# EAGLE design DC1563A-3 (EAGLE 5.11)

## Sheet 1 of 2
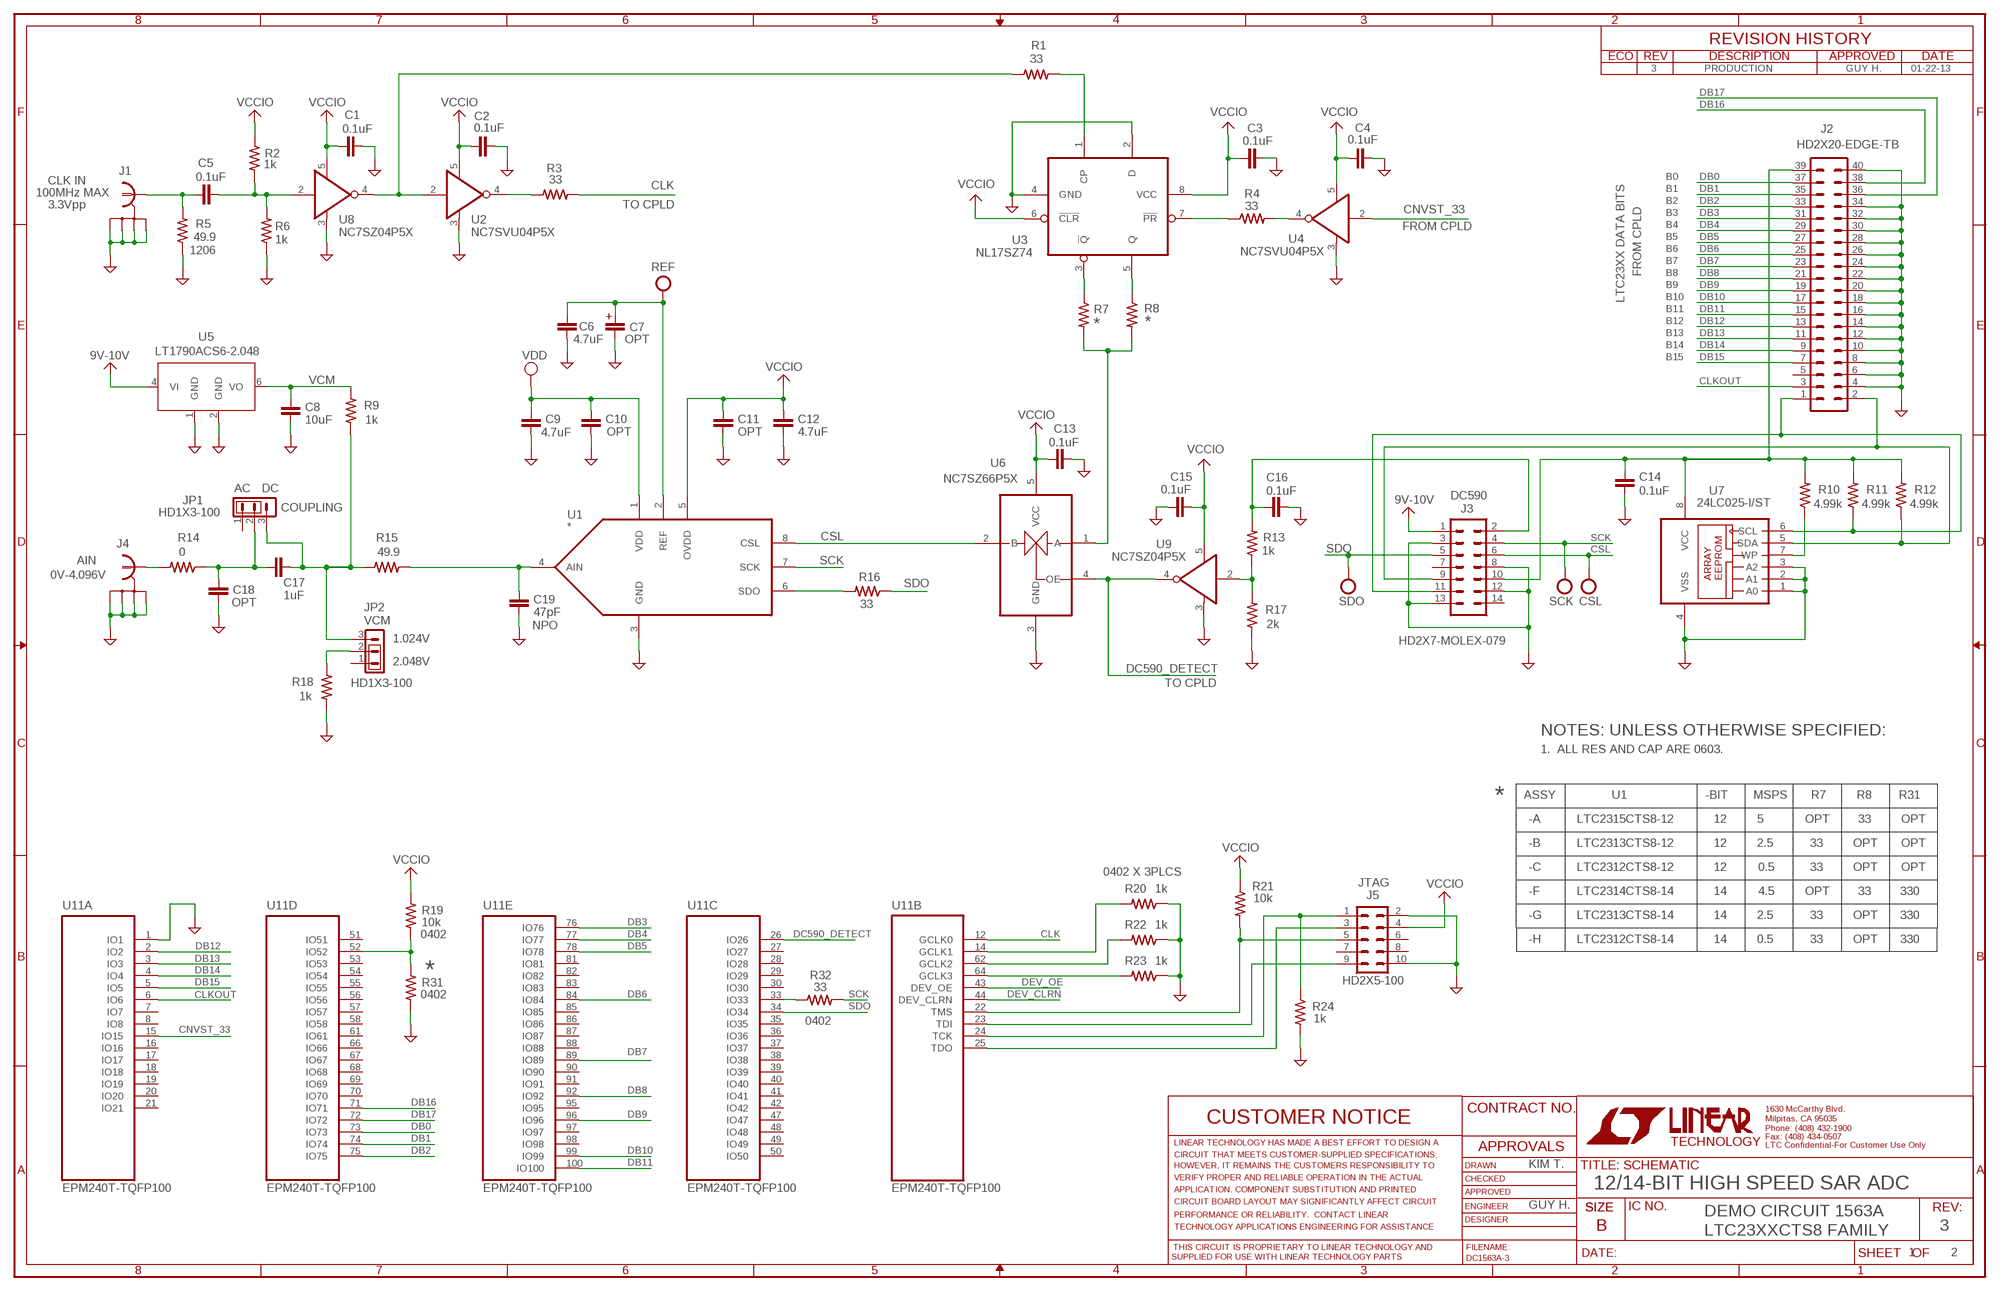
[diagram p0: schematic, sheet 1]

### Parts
C1  0.1uF  CAP-NP-SMT-0603  [0603]
C2  0.1uF  CAP-NP-SMT-0603  [0603]
C3  0.1uF  CAP-NP-SMT-0603  [0603]
C4  0.1uF  CAP-NP-SMT-0603  [0603]
C5  0.1uF  CAP-NP-SMT-0603  [0603]
C6  4.7uF  CAP-NP-SMT-0603  [0603]
C7  OPT  CAP-P-0603  [0603]
C8  10uF  CAP-NP-SMT-0603  [0603]
C9  4.7uF  CAP-NP-SMT-0603  [0603]
C10  OPT  CAP-NP-SMT-0603  [0603]
C11  OPT  CAP-NP-SMT-0603  [0603]
C12  4.7uF  CAP-NP-SMT-0603  [0603]
C13  0.1uF  CAP-NP-SMT-0603  [0603]
C14  0.1uF  CAP-NP-SMT-0603  [0603]
C15  0.1uF  CAP-NP-SMT-0603  [0603]
C16  0.1uF  CAP-NP-SMT-0603  [0603]
C17  1uF  CAP-NP-SMT-0603  [0603]
C18  OPT  CAP-NP-SMT-0603  [0603]
C19  47pF  CAP-NP-SMT-0603  [0603]
CSL  E-35-60  [PAD-35-60]
J1  BNC-5PINS  [BNC-112404]
J2  HD2X20-EDGE-TB  [CON-EDGE40-100]
J3  HD2X7-MOLEX-079  [HD2X7-079-MOLEX]
J4  BNC-5PINS  [BNC-112404]
J5  HD2X5-100  [HD2X5-100]
JP1  HD1X3-100  [HD1X3-100]
JP2  HD1X3-100  [HD1X3-100]
R1  33  RES-0603  [0603]
R2  1k  RES-0603  [0603]
R3  33  RES-0603  [0603]
R4  33  RES-0603  [0603]
R5  49.9  RES-1206  [1206]
R6  1k  RES-0603  [0603]
R7  *  RES-0603  [0603]
R8  *  RES-0603  [0603]
R9  1k  RES-0603  [0603]
R10  4.99k  RES-0603  [0603]
R11  4.99k  RES-0603  [0603]
R12  4.99k  RES-0603  [0603]
R13  1k  RES-0603  [0603]
R14  0  RES-0603  [0603]
R15  49.9  RES-0603  [0603]
R16  33  RES-0603  [0603]
R17  2k  RES-0603  [0603]
R18  1k  RES-0603  [0603]
R19  10k  RES-0402  [0402]
R20  1k  RES-0402  [0402]
R21  10k  RES-0603  [0603]
R22  1k  RES-0402  [0402]
R23  1k  RES-0402  [0402]
R24  1k  RES-0603  [0603]
R31  OPT  RES-0402  [0402]
R32  33  RES-0402  [0402]
REF  E-35-60  [PAD-35-60]
SCK  E-35-60  [PAD-35-60]
SDO  E-35-60  [PAD-35-60]
U1  *  LTC23XXCTS8  [TSOT23-8]
U2  NC7SVU04P5X  [SC70-5]
U3  NL17SZ74  [US8]
U4  NC7SVU04P5X  NC7ST04P5X  [SC70-5]
U5  LT1790ACS6-2.048  [SOT23-6]
U6  NC7SZ66P5X  [SC70-5]
U7  24LC025-I/ST  [TSSOP8]
U8  NC7SZ04P5X  [SC70-5]
U9  NC7SZ04P5X  [SC70-5]
U11  EPM240T-TQFP100  [TQFP100]

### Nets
9V-10V: J3.1 U5.4(VI) ; also sheet 2
CLK: R3.2 U11.12(B:GCLK0)
CLKOUT: J2.3 U11.6(A:IO6)
CNVST_33: U4.2(A) U11.15(A:IO15)
CSL: CSL.1 J3.6 U1.8(CSL) U6.2(B)
DB0: J2.37 U11.73(D:IO73)
DB1: J2.35 U11.74(D:IO74)
DB2: J2.33 U11.75(D:IO75)
DB3: J2.31 U11.76(E:IO76)
DB4: J2.29 U11.77(E:IO77)
DB5: J2.27 U11.78(E:IO78)
DB6: J2.25 U11.84(E:IO84)
DB7: J2.23 U11.89(E:IO89)
DB8: J2.21 U11.92(E:IO92)
DB9: J2.19 U11.96(E:IO96)
DB10: J2.17 U11.99(E:IO99)
DB11: J2.15 U11.100(E:IO100)
DB12: J2.13 U11.2(A:IO2)
DB13: J2.11 U11.3(A:IO3)
DB14: J2.9 U11.4(A:IO4)
DB15: J2.7 U11.5(A:IO5)
DB16: J2.38 U11.71(D:IO71)
DB17: J2.36 U11.72(D:IO72)
DC590_DETECT: U6.4(OE) U9.4(Y) U11.26(C:IO26)
DC590VP: C16.1 J3.2 R13.2
DEV_CLRN: U11.44(B:DEV_CLRN)
DEV_OE: U11.43(B:DEV_OE)
GND: C1.2 C2.2 C3.2 C4.2 C6.1 C7.2 C8.1 C9.1 C10.1 C11.1 C12.1 C13.2 C14.2 C15.1 C16.2 C18.2 C19.2 J1.2(GND) J1.3(GND) J1.4(GND) J1.5(GND) J2.4 J2.6 J2.8 J2.10 J2.12 J2.14 J2.16 J2.18 J2.20 J2.22 J2.24 J2.26 J2.28 J2.30 J2.32 J2.34 J2.40 J3.3 J3.8 J3.12 J3.13 J4.2(GND) J4.3(GND) J4.4(GND) J4.5(GND) J5.2 J5.10 R5.1 R6.1 R17.1 R18.1 R20.1 R22.1 R23.1 R24.2 R31.1 U1.3(GND) U2.3(GND) U3.2(D) U3.4(GND) U4.3(GND) U5.1(GND) U5.2(GND) U6.3(GND) U7.1(A0) U7.2(A1) U7.3(A2) U7.4(VSS) U8.3(GND) U9.3(GND) U11.1(A:IO1) ; also sheet 2
N$1: C17.1 C18.1 JP1.2 R14.1
N$2: J4.1 R14.2
N$3: J5.9 U11.23(B:TDI)
N$4: J5.1 R24.1 U11.24(B:TCK)
N$5: J5.3 U11.25(B:TDO)
N$6: J5.5 R21.2 U11.22(B:TMS)
N$9: R23.2 U11.64(B:GCLK3)
N$10: R7.1 U3.3(!Q)
N$11: R19.1 R31.2 U11.52(D:IO52)
N$12: R8.1 U3.5(Q)
N$13: R13.1 R17.2 U9.2(A)
N$15: R32.1 U11.33(C:IO33)
N$17: R10.1 U7.7(WP)
N$19: J2.1 J3.11 R11.1 U7.6(SCL)
N$23: R4.1 U3.7(!PR)
N$24: JP2.2 R18.2
N$25: R4.2 U4.4(Y)
N$26: C17.2 JP1.3 JP2.3 R9.1 R15.2
N$27: C5.1 J1.1 R5.2
N$28: C5.2 R2.1 R6.2 U8.2(A)
N$29: R1.2 U3.1(CP)
N$30: R22.2 U11.62(B:GCLK2)
N$31: R3.1 U2.4(Y)
N$32: R16.2 U1.6(SDO)
N$34: J2.2 J3.9 R12.1 U7.5(SDA)
N$36: R1.1 U2.2(A) U8.4(Y)
N$39: C6.2 C7.1 REF.1 U1.2(REF)
N$41: R7.2 R8.2 U6.1(A)
N$44: C19.1 R15.1 U1.4(AIN)
N$45: C14.1 J2.39 J3.10 R10.2 R11.2 R12.2 U7.8(VCC)
N$51: R20.2 U11.14(B:GCLK1)
SCK: J3.4 R32.2 SCK.1 U1.7(SCK)
SDO: J3.5 R16.1 SDO.1 U11.34(C:IO34)
VCCIO: C1.1 C2.1 C3.1 C4.1 C11.2 C12.2 C13.1 C15.2 J5.4 R2.2 R19.2 R21.1 U1.5(OVDD) U2.5(VCC) U3.6(!CLR) U3.8(VCC) U4.5(VCC) U6.5(VCC) U8.5(VCC) U9.5(VCC) ; also sheet 2
VCM: C8.2 R9.2 U5.6(VO)
VDD: C9.2 C10.2 U1.1(VDD) ; also sheet 2
Unconnected: J2.5 J3.7 J3.14 J5.6 J5.7 J5.8 JP1.1 JP2.1 U2.1(NC) U4.1(NC) U8.1(NC) U9.1(NC) U11.7(A:IO7) U11.8(A:IO8) U11.16(A:IO16) U11.17(A:IO17) U11.18(A:IO18) U11.19(A:IO19) U11.20(A:IO20) U11.21(A:IO21) U11.27(C:IO27) U11.28(C:IO28) U11.29(C:IO29) U11.30(C:IO30) U11.35(C:IO35) U11.36(C:IO36) U11.37(C:IO37) U11.38(C:IO38) U11.39(C:IO39) U11.40(C:IO40) U11.41(C:IO41) U11.42(C:IO42) U11.47(C:IO47) U11.48(C:IO48) U11.49(C:IO49) U11.50(C:IO50) U11.51(D:IO51) U11.53(D:IO53) U11.54(D:IO54) U11.55(D:IO55) U11.56(D:IO56) U11.57(D:IO57) U11.58(D:IO58) U11.61(D:IO61) U11.66(D:IO66) U11.67(D:IO67) U11.68(D:IO68) U11.69(D:IO69) U11.70(D:IO70) U11.81(E:IO81) U11.82(E:IO82) U11.83(E:IO83) U11.85(E:IO85) U11.86(E:IO86) U11.87(E:IO87) U11.88(E:IO88) U11.90(E:IO90) U11.91(E:IO91) U11.95(E:IO95) U11.97(E:IO97) U11.98(E:IO98)

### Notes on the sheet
- 3 | PRODUCTION | GUY H. | 01-22-13
- B0
- CLK IN
- B1
- 100MHz MAX
- B2
- 3.3Vpp | TO CPLD
- B3
- FROM CPLD | B4
- B5
- 1206 | B6
- B7
- FROM CPLD | B8
- B9
- LTC23XX DATA BITS | B10
- B11
- B12
- B13
- B14
- B15
- AC | DC
- DC590
- COUPLING
- AIN
- 0V-4.096V
- VCM
- NPO
- 1.024V
- 2.048V
- TO CPLD
- NOTES: UNLESS OTHERWISE SPECIFIED:
- 1.  ALL RES AND CAP ARE 0603.
- ASSY | U1 | -BIT | MSPS | R7 | R8 | R31
- *
- -A | LTC2315CTS8-12 | 12 | 5 | OPT | 33 | OPT
- -B | LTC2313CTS8-12 | 12 | 2.5 | 33 | OPT | OPT
- -C | LTC2312CTS8-12 | 12 | 0.5 | 33 | OPT | OPT
- 0402 X 3PLCS
- JTAG
- -F | LTC2314CTS8-14 | 14 | 4.5 | OPT | 33 | 330
- -G | LTC2313CTS8-14 | 14 | 2.5 | 33 | OPT | 330
- 0402
- -H | LTC2312CTS8-14 | 14 | 0.5 | 33 | OPT | 330
- *
- 0402
- 0402
- KIM T.
- 12/14-BIT HIGH SPEED SAR ADC
- GUY H.
- DEMO CIRCUIT 1563A
- 3
- LTC23XXCTS8 FAMILY
- 1 | 2

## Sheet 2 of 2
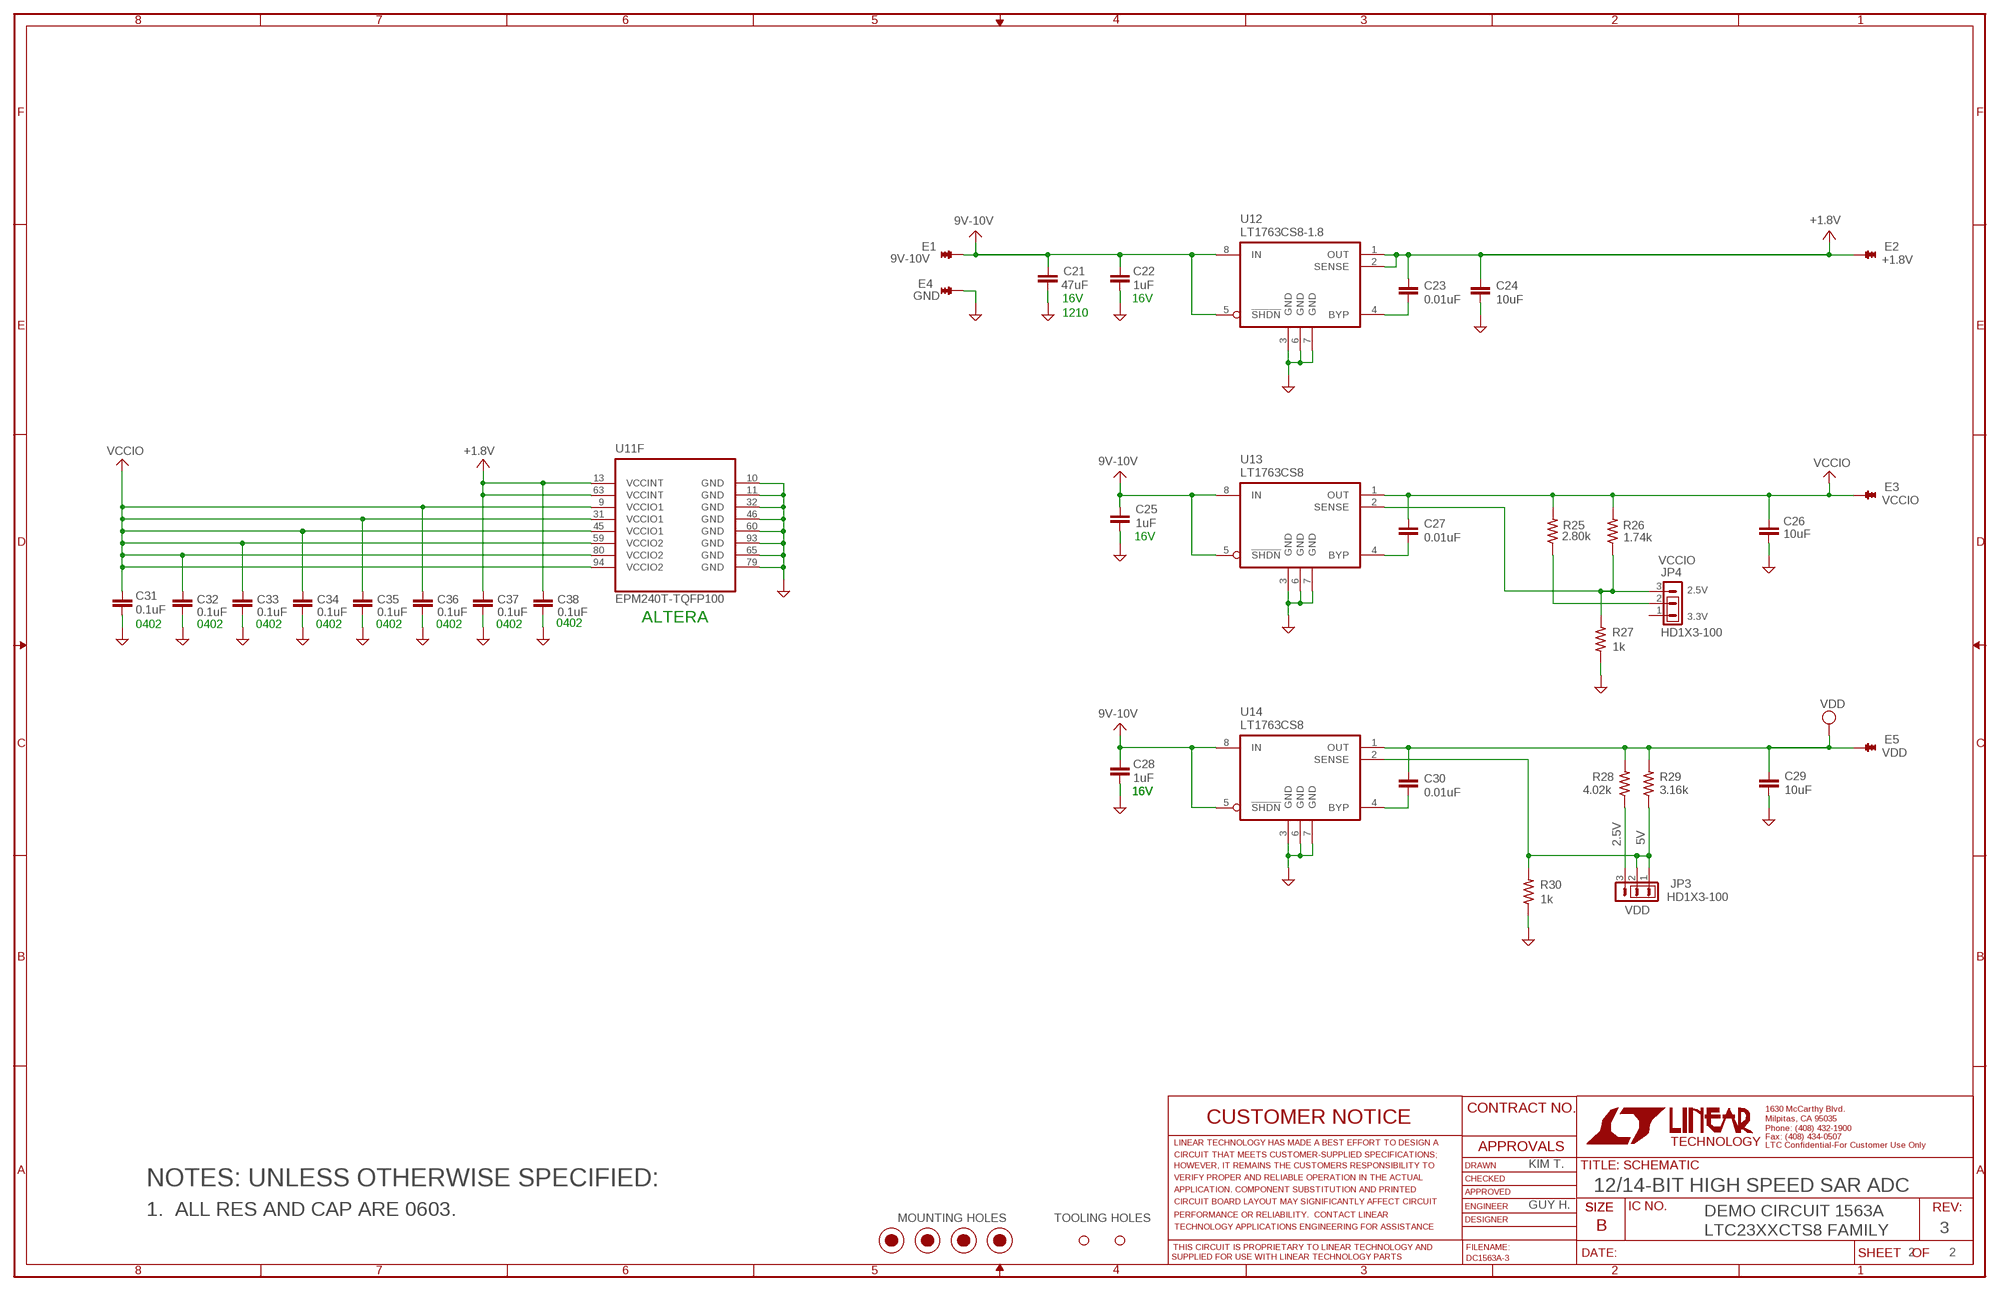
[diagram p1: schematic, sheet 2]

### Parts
C21  47uF  CAP-NP-SMT-1210  [1210]
C22  1uF  CAP-NP-SMT-0603  [0603]
C23  0.01uF  CAP-NP-SMT-0603  [0603]
C24  10uF  CAP-NP-SMT-0603  [0603]
C25  1uF  CAP-NP-SMT-0603  [0603]
C26  10uF  CAP-NP-SMT-0603  [0603]
C27  0.01uF  CAP-NP-SMT-0603  [0603]
C28  1uF  CAP-NP-SMT-0603  [0603]
C29  10uF  CAP-NP-SMT-0603  [0603]
C30  0.01uF  CAP-NP-SMT-0603  [0603]
C31  0.1uF  CAP-NP-SMT-0402  [0402]
C32  0.1uF  CAP-NP-SMT-0402  [0402]
C33  0.1uF  CAP-NP-SMT-0402  [0402]
C34  0.1uF  CAP-NP-SMT-0402  [0402]
C35  0.1uF  CAP-NP-SMT-0402  [0402]
C36  0.1uF  CAP-NP-SMT-0402  [0402]
C37  0.1uF  CAP-NP-SMT-0402  [0402]
C38  0.1uF  CAP-NP-SMT-0402  [0402]
E1  TURRET-094  [MILLMAX-2501-2]
E2  TURRET0.063  TURRET-064  [MILLMAX-2308-2]
E3  TURRET0.063  TURRET-064  [MILLMAX-2308-2]
E4  TURRET-094  [MILLMAX-2501-2]
E5  TURRET0.063  TURRET-064  [MILLMAX-2308-2]
JP3  HD1X3-100  [HD1X3-100]
JP4  HD1X3-100  [HD1X3-100]
MTG1  MTG-8831-8831  MTG-8831-STANDOFF  [MTG-8831]
MTG2  MTG-8831-8831  MTG-8831-STANDOFF  [MTG-8831]
MTG3  MTG-8831-8831  MTG-8831-STANDOFF  [MTG-8831]
MTG4  MTG-8831-8831  MTG-8831-STANDOFF  [MTG-8831]
R25  2.80k  RES-0603  [0603]
R26  1.74k  RES-0603  [0603]
R27  1k  RES-0603  [0603]
R28  4.02k  RES-0603  [0603]
R29  3.16k  RES-0603  [0603]
R30  1k  RES-0603  [0603]
U12  LT1763CS8-1.8  LT1763-1.8CS8  [SO8]
U13  LT1763CS8  [SO8]
U14  LT1763CS8  [SO8]
X1  TOOLINGHOLE-70MIL  [TOOLINGHOLE]
X2  TOOLINGHOLE-70MIL  [TOOLINGHOLE]

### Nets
9V-10V: C21.1 C22.1 C25.1 C28.1 E1.1 U12.5(!SHDN) U12.8(IN) U13.5(!SHDN) U13.8(IN) U14.5(!SHDN) U14.8(IN) ; also sheet 1
+1.8V: C23.1 C24.1 C37.1 C38.1 E2.1 U11.13(F:VCCINT) U11.63(F:VCCINT) U12.1(OUT) U12.2(SENSE)
GND: C21.2 C22.2 C24.2 C25.2 C26.2 C28.2 C29.2 C31.2 C32.2 C33.2 C34.2 C35.2 C36.2 C37.2 C38.2 E4.1 R27.1 R30.1 U11.10(F:GND) U11.11(F:GND) U11.32(F:GND) U11.46(F:GND) U11.60(F:GND) U11.65(F:GND) U11.79(F:GND) U11.93(F:GND) U12.3(GND) U12.6(GND) U12.7(GND) U13.3(GND) U13.6(GND) U13.7(GND) U14.3(GND) U14.6(GND) U14.7(GND) ; also sheet 1
N$7: JP4.3 R26.1 R27.2 U13.2(SENSE)
N$14: JP4.2 R25.1
N$18: JP3.1 JP3.2 R29.1 R30.2 U14.2(SENSE)
N$20: JP3.3 R28.1
N$50: C27.2 U13.4(BYP)
N$53: C23.2 U12.4(BYP)
N$57: C30.2 U14.4(BYP)
VCCIO: C26.1 C27.1 C31.1 C32.1 C33.1 C34.1 C35.1 C36.1 E3.1 R25.2 R26.2 U11.9(F:VCCIO1) U11.31(F:VCCIO1) U11.45(F:VCCIO1) U11.59(F:VCCIO2) U11.80(F:VCCIO2) U11.94(F:VCCIO2) U13.1(OUT) ; also sheet 1
VDD: C29.1 C30.1 E5.1 R28.2 R29.2 U14.1(OUT) ; also sheet 1
Unconnected: JP4.1 MTG1.1 MTG2.1 MTG3.1 MTG4.1 X1.1 X2.1

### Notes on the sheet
- 9V-10V | +1.8V
- GND | 16V | 16V
- 1210
- VCCIO
- 16V
- VCCIO
- 2.5V
- ALTERA | 3.3V
- 0402 | 0402 | 0402 | 0402 | 0402 | 0402 | 0402 | 0402
- VDD
- 16V | 16V
- 2.5V | 5V
- VDD
- KIM T.
- NOTES: UNLESS OTHERWISE SPECIFIED:
- 12/14-BIT HIGH SPEED SAR ADC
- GUY H.
- 1.  ALL RES AND CAP ARE 0603. | DEMO CIRCUIT 1563A
- MOUNTING HOLES | TOOLING HOLES
- LTC23XXCTS8 FAMILY | 3
- 2 | 2

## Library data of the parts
C1-C6 C8-C19 C21-C38 = LTDB_Passives:CAP-NP-SMT-: Capacitor; Non-polar; SMT
C7 = EagleLib:CAP-P: Capacitor; Non-polar; SMT
CSL SCK SDO = LTDB_Connectors:E-35-60
E1-E5 = LTDB_Connectors:TURRET: Turret
J1 J4 = LTDB_Connectors:BNC-5PINS: BNC CONNECTOR M/A COM www.macom.com distributor Farnell 149-452
J2 = EagleLib:HD2X20
J3 = LTDB_Connectors:HD2X7-MOLEX: HDR-7x2-Pin-Straight-Shrouded Molex 87331-1420
J5 = EagleLib:HD2X5
JP1-JP3 = LTDB_Connectors:HD1X3: Jumper,3pin, point connections
JP4 = EagleLib:HD1X3: Jumper,3pin, point connections
MTG1-MTG4 = LTDB_Connectors:MTG-8831
R1-R32 = LTDB_Passives:RES-: Resistor; GP
REF = DC1563A:E-35-60
U1 = EagleLib:LTC23XXCTS8
U2 = LTDB_ICs:NC7SVU04
U3 = LTDB_ICs:NL17SZ74
U4 = LTDB_ICs:NC7ST04
U5 = LTDB_Linear_Parts:LT1790?-*: Voltage Reference;Series
U6 = LTDB_ICs:NC7SZ66
U7 = LTDB_ICs:24LC025
U8 U9 = LTDB_ICs:NC7SZ04
U11 = LTDB_ICs:EPM240T-TQFP100
U12-U14 = LTDB_Linear_Parts:LT1763: 500MA, Low Noise, LDO Micropwer Regulator
X1 X2 = LTDB_Connectors:TOOLINGHOLE

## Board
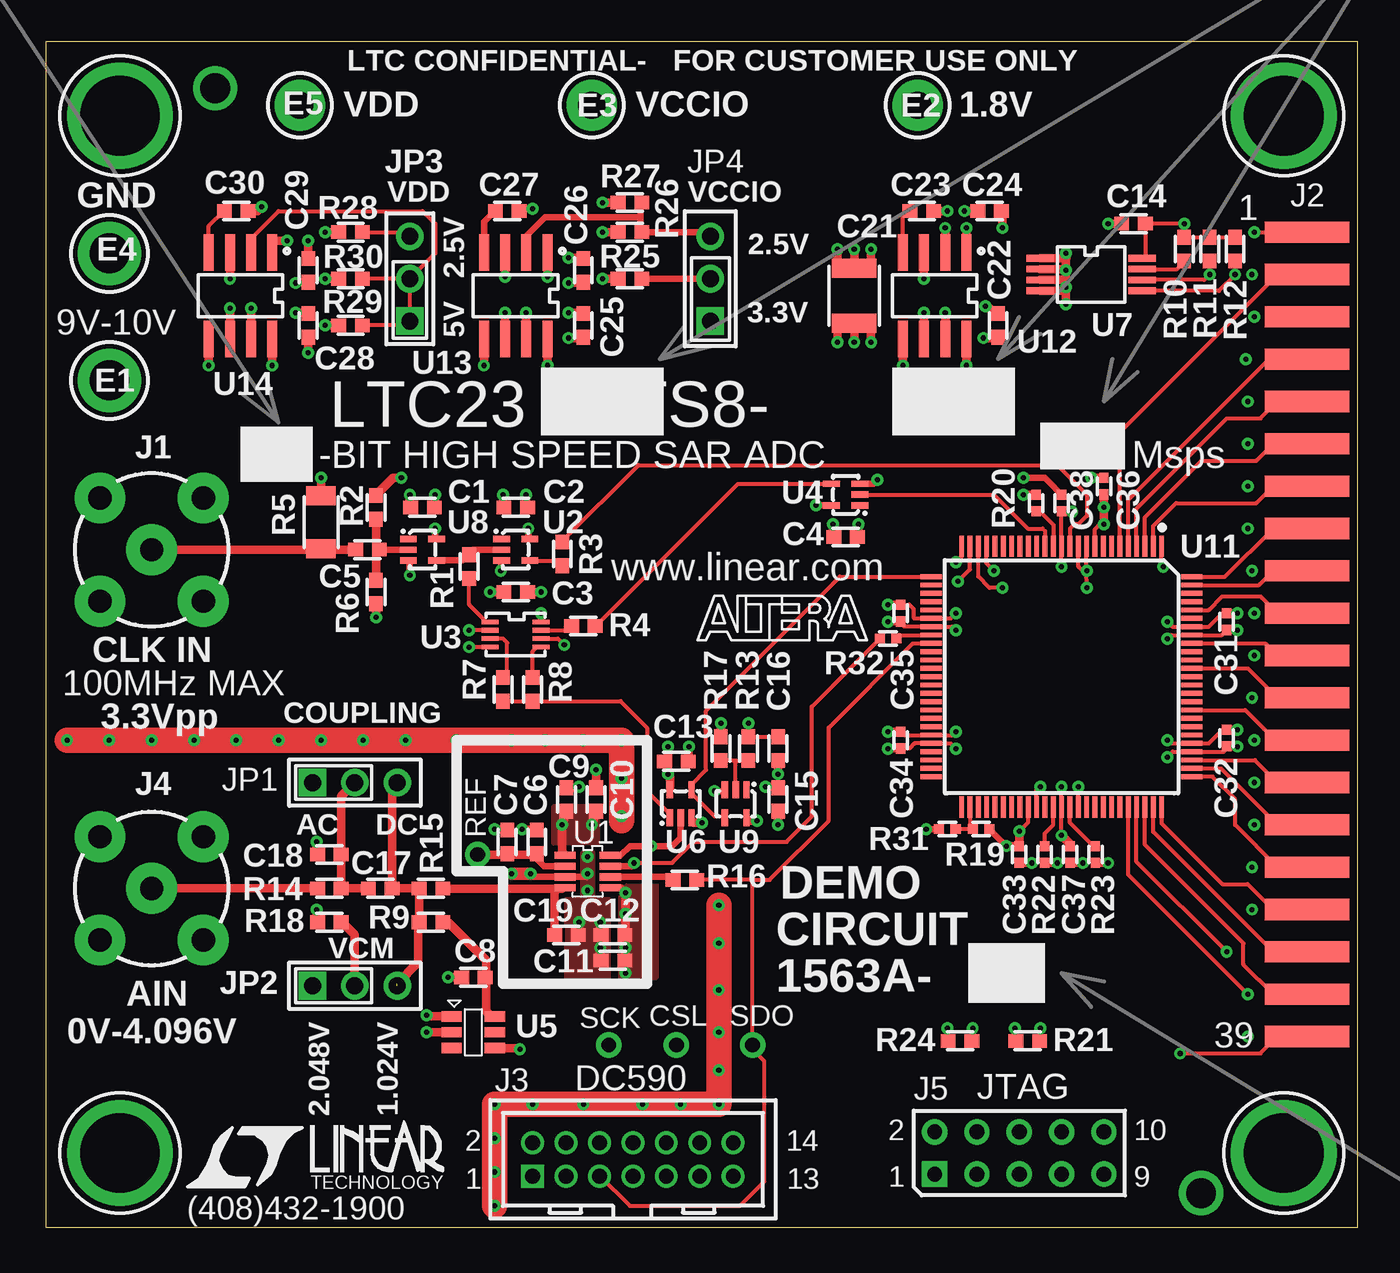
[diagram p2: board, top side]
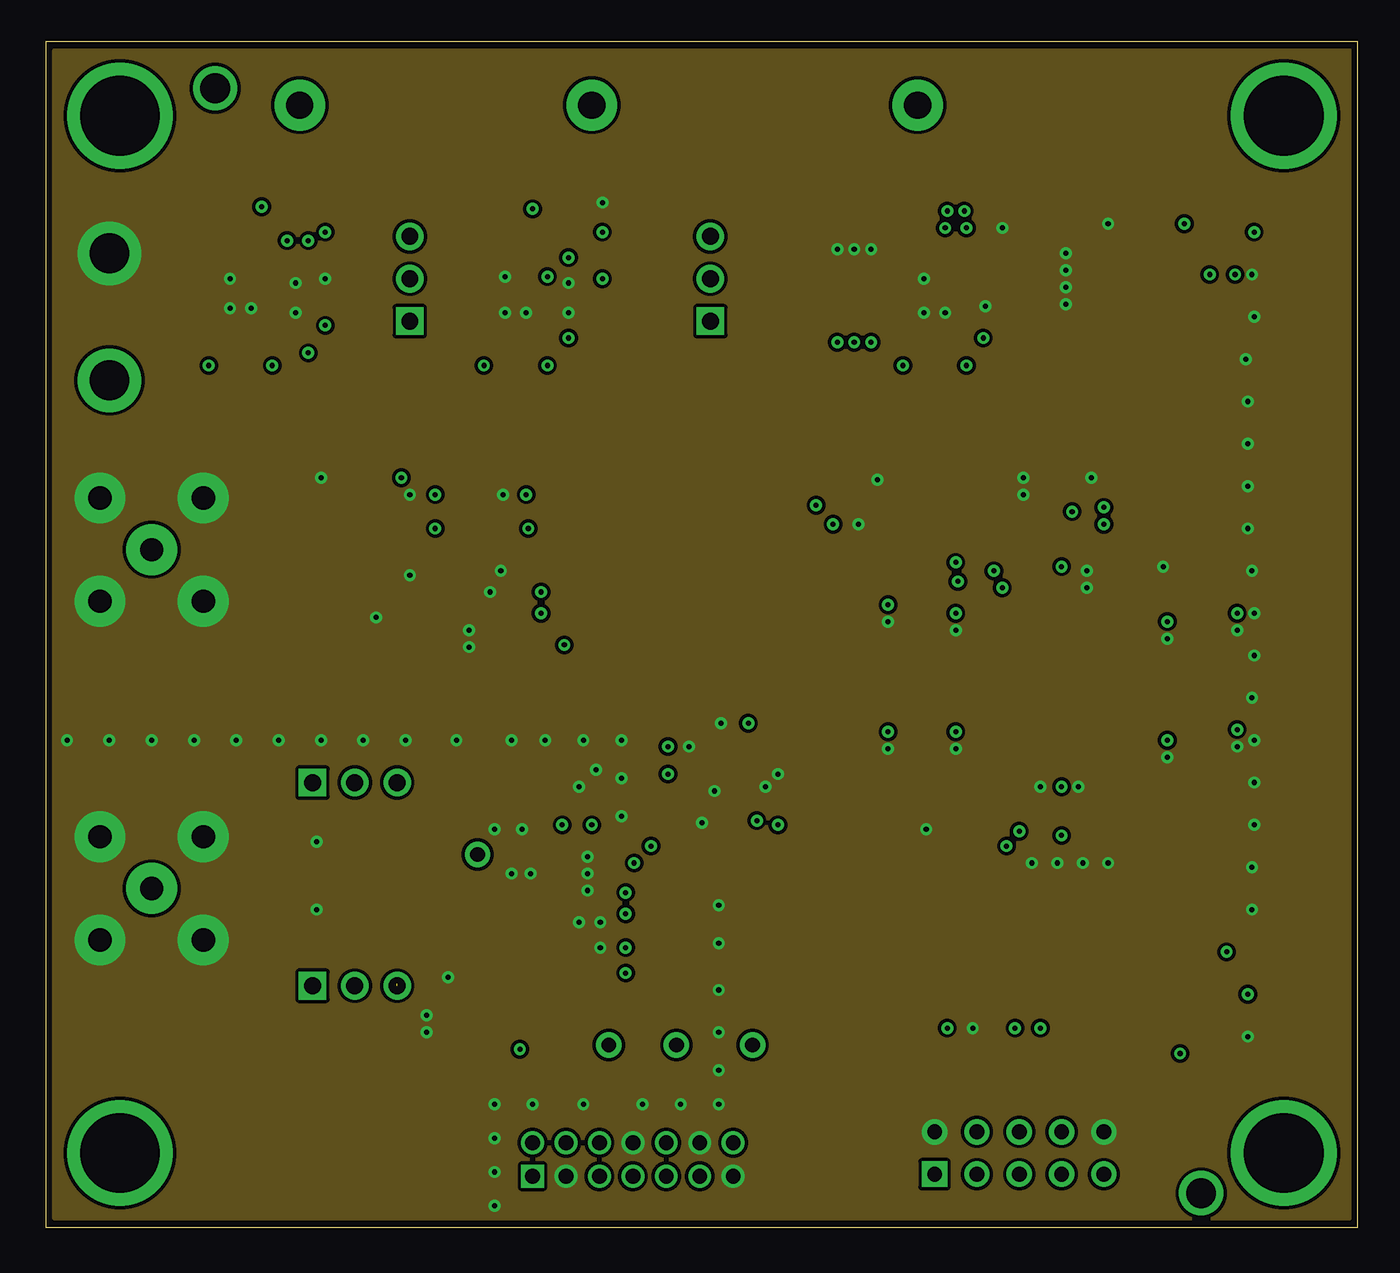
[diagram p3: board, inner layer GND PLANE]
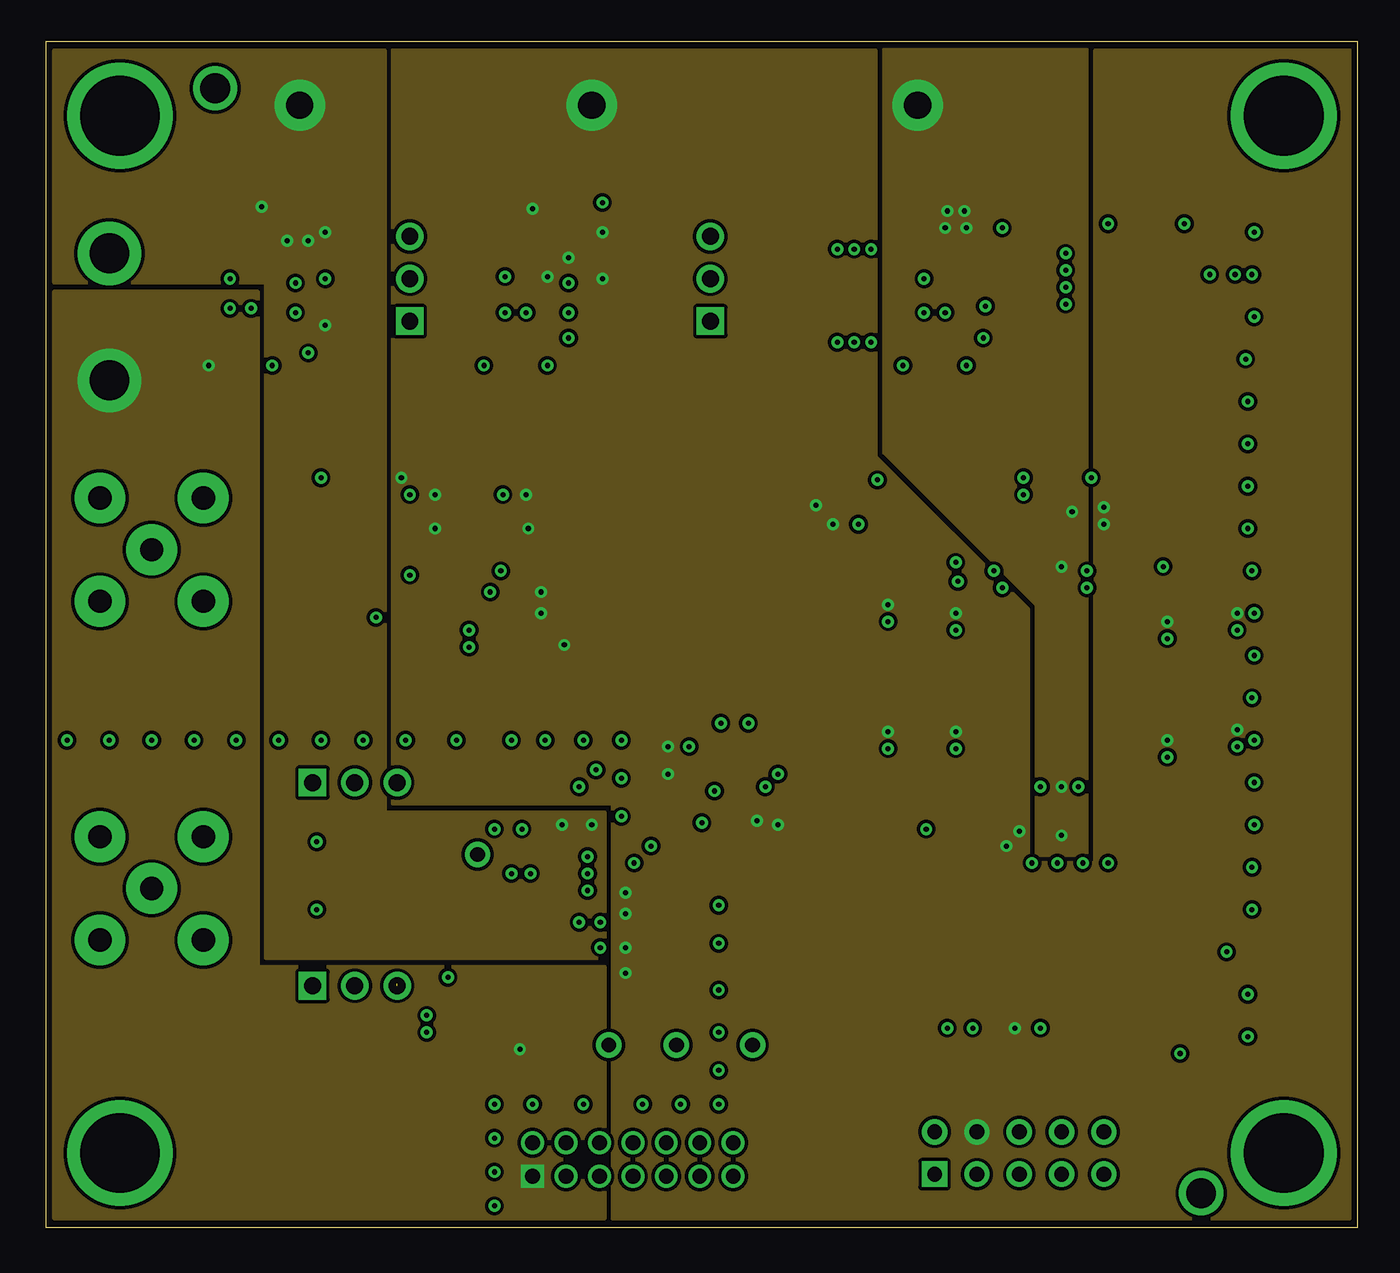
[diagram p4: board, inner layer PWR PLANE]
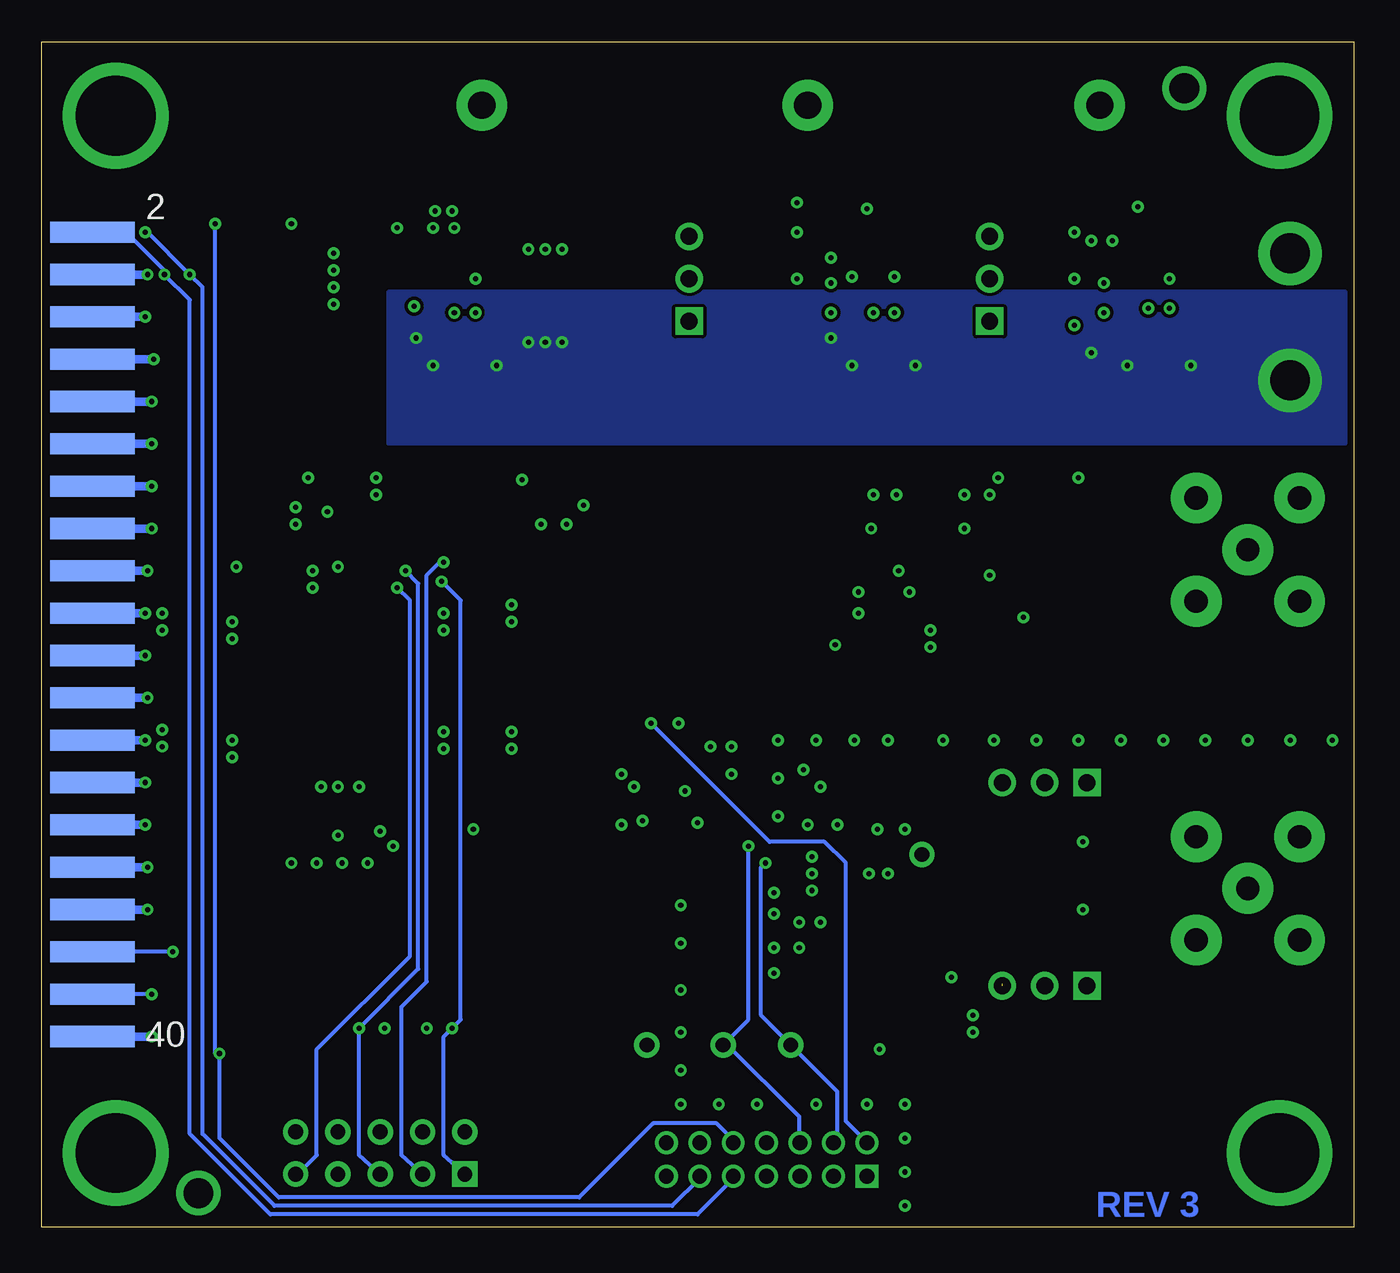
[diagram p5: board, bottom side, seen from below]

Size 78.74 x 71.12 mm. Coordinates in mm from the lower left corner, seen from the top.
Outline: 0,0 78.74,0 78.74,71.12 0,71.12 0,0
Copper layers (1*2+3*16): TOP 0.0508mm / dielectric 0.4318mm / GND PLANE 0.0254mm / dielectric 0.7112mm / PWR PLANE 0.0254mm / dielectric 0.3048mm / BOTTOM 0.0508mm
Design rules "Kim-Design Rules": minimum track width 10mil, minimum drill 12mil, track to track 8mil, track to pad 8mil, pad to pad 8mil, via to via 8mil, smd to smd 0mil, copper to edge 10mil, drill to drill 10mil, minimum pad ring 8mil, minimum via ring 8mil, stop-mask expansion 4mil, vias tented up to drill 15mil, thermal gap 10mil

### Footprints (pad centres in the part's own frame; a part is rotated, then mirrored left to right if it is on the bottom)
0603 = smd 0.889 x 0.813: 1 -0.71,0; 2 0.71,0
1210 = smd 1.143 x 2.667: 1 -1.641,0; 2 1.641,0
0402 = smd 0.61 x 0.559: 1 -0.498,0; 2 0.498,0
PAD-35-60 = drill 0.889 pad 1.524 round: 1 0,0
MILLMAX-2501-2 = drill 2.388 pad 3.81 round: 1 0,0
MILLMAX-2308-2 = drill 1.626 pad 3.048 round: 1 0,0
BNC-112404 = drill 1.397 pad 3.048 round: 1 0,0; 2 3.099,3.099; 3 -3.099,3.099; 4 -3.099,-3.099; 5 3.099,-3.099
CON-EDGE40-100 = smd 5.08 x 1.27: 1 0,24.13; 3 0,21.59; 5 0,19.05; 7 0,16.51; 9 0,13.97; 11 0,11.43; 13 0,8.89; 15 0,6.35; 17 0,3.81; 19 0,1.27; 21 0,-1.27; 23 0,-3.81; 25 0,-6.35; 27 0,-8.89; 29 0,-11.43; 31 0,-13.97; 33 0,-16.51; 35 0,-19.05; 37 0,-21.59; 39 0,-24.13 | smd 5.08 x 1.27 bottom: 2 0,24.13; 4 0,21.59; 6 0,19.05; 8 0,16.51; 10 0,13.97; 12 0,11.43; 14 0,8.89; 16 0,6.35; 18 0,3.81; 20 0,1.27; 22 0,-1.27; 24 0,-3.81; 26 0,-6.35; 28 0,-8.89; 30 0,-11.43; 32 0,-13.97; 34 0,-16.51; 36 0,-19.05; 38 0,-21.59; 40 0,-24.13
HD2X7-079-MOLEX = drill 0.889 pad 1.372 square: 1 0,0 | drill 0.889 pad 1.372 round: 2 0,2.007; 3 2.007,0; 4 2.007,2.007; 5 4.013,0; 6 4.013,2.007; 7 6.02,0; 8 6.02,2.007; 9 8.026,0; 10 8.026,2.007; 11 10.033,0; 12 10.033,2.007; 13 12.04,0; 14 12.04,2.007
HD2X5-100 = drill 0.889 pad 1.524 square: 1 0,0 | drill 0.889 pad 1.524 round: 2 0,2.54; 3 2.54,0; 4 2.54,2.54; 5 5.08,0; 6 5.08,2.54; 7 7.62,0; 8 7.62,2.54; 9 10.16,0; 10 10.16,2.54
HD1X3-100 = drill 1.016 pad 1.651 square: 1 0,0 | drill 1.016 pad 1.651 round: 2 2.54,0; 3 5.08,0
MTG-8831 = drill 4.775 pad 6.35 round: 1 0,0
1206 = smd 1.143 x 1.778: 1 -1.591,0; 2 1.591,0
TSOT23-8 = smd 0.432 x 1.27: 1 -0.97,-1.36; 2 -0.32,-1.36; 3 0.33,-1.36; 4 0.98,-1.36; 5 0.98,1.363; 6 0.33,1.363; 7 -0.32,1.363; 8 -0.97,1.363
SC70-5 = smd 0.381 x 1.016: 1 -0.65,-0.85; 2 0,-0.85; 3 0.65,-0.85; 4 0.65,0.85; 5 -0.65,0.85
US8 = smd 0.279 x 1.016: 1 -0.75,-1.527; 2 -0.25,-1.527; 3 0.25,-1.527; 4 0.75,-1.527; 5 0.75,1.527; 6 0.25,1.527; 7 -0.25,1.527; 8 -0.75,1.527
SOT23-6 = smd 0.62 x 1.22: 1 -0.95,-1.3; 2 0,-1.3; 3 0.95,-1.3; 4 0.95,1.3; 5 0,1.3; 6 -0.95,1.3
TSSOP8 = smd 0.406 x 1.651: 1 -0.975,-3.052; 2 -0.325,-3.052; 3 0.325,-3.052; 4 0.975,-3.052; 5 0.975,3.052; 6 0.325,3.052; 7 -0.325,3.052; 8 -0.975,3.052
TQFP100 = smd 1.27 x 0.292: 1 -7.822,6; 2 -7.822,5.5; 3 -7.822,5; 4 -7.822,4.5; 5 -7.822,4; 6 -7.822,3.5; 7 -7.822,3; 8 -7.822,2.5; 9 -7.822,2; 10 -7.822,1.5; 11 -7.822,1; 12 -7.822,0.5; 13 -7.822,0; 14 -7.822,-0.5; 15 -7.822,-1; 16 -7.822,-1.5; 17 -7.822,-2; 18 -7.822,-2.5; 19 -7.822,-3; 20 -7.822,-3.5; 21 -7.822,-4; 22 -7.822,-4.5; 23 -7.822,-5; 24 -7.822,-5.5; 25 -7.822,-6; 51 7.822,-6; 52 7.822,-5.5; 53 7.822,-5; 54 7.822,-4.5; 55 7.822,-4; 56 7.822,-3.5; 57 7.822,-3; 58 7.822,-2.5; 59 7.822,-2; 60 7.822,-1.5; 61 7.822,-1; 62 7.822,-0.5; 63 7.822,0; 64 7.822,0.5; 65 7.822,1; 66 7.822,1.5; 67 7.822,2; 68 7.822,2.5; 69 7.822,3; 70 7.822,3.5; 71 7.822,4; 72 7.822,4.5; 73 7.822,5; 74 7.822,5.5; 75 7.822,6 | smd 0.292 x 1.27: 26 -6,-7.822; 27 -5.5,-7.822; 28 -5,-7.822; 29 -4.5,-7.822; 30 -4,-7.822; 31 -3.5,-7.822; 32 -3,-7.822; 33 -2.5,-7.822; 34 -2,-7.822; 35 -1.5,-7.822; 36 -1,-7.822; 37 -0.5,-7.822; 38 0,-7.822; 39 0.5,-7.822; 40 1,-7.822; 41 1.5,-7.822; 42 2,-7.822; 43 2.5,-7.822; 44 3,-7.822; 45 3.5,-7.822; 46 4,-7.822; 47 4.5,-7.822; 48 5,-7.822; 49 5.5,-7.822; 50 6,-7.822; 76 6,7.822; 77 5.5,7.822; 78 5,7.822; 79 4.5,7.822; 80 4,7.822; 81 3.5,7.822; 82 3,7.822; 83 2.5,7.822; 84 2,7.822; 85 1.5,7.822; 86 1,7.822; 87 0.5,7.822; 88 0,7.822; 89 -0.5,7.822; 90 -1,7.822; 91 -1.5,7.822; 92 -2,7.822; 93 -2.5,7.822; 94 -3,7.822; 95 -3.5,7.822; 96 -4,7.822; 97 -4.5,7.822; 98 -5,7.822; 99 -5.5,7.822; 100 -6,7.822
SO8@1 = smd 0.6 x 2.2: 1 -1.905,-2.6; 2 -0.635,-2.6; 3 0.635,-2.6; 4 1.905,-2.6; 5 1.905,2.6; 6 0.635,2.6; 7 -0.635,2.6; 8 -1.905,2.6
TOOLINGHOLE = drill 1.778 pad 1.778 round: 1 0,0

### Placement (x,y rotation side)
C1  22.61,43.18 180 top
C2  28.19,43.18 180 top
C3  28.19,38.1 180 top
C4  48.01,41.4 0 top
C5  19.3,40.64 0 top
C6  29.46,23.11 270 top
C7  27.69,23.11 90 top
C8  25.65,14.99 0 top
C9  31.24,25.65 270 top
C10  33.02,25.65 270 top
C11  34.04,16 0 top
C12  34.04,17.53 0 top
C13  37.85,27.94 0 top
C14  65.28,60.2 180 top
C15  43.94,25.65 270 top
C16  43.94,28.7 270 top
C17  20.07,20.32 0 top
C18  17.02,22.35 180 top
C19  31.24,17.53 0 top
C21  48.51,55.88 90 top
C22  57.15,54.1 90 top
C23  52.58,60.96 180 top
C24  56.64,60.96 0 top
C25  32.26,54.1 90 top
C26  32.26,57.4 270 top
C27  27.69,60.96 180 top
C28  15.75,54.1 90 top
C29  15.75,57.4 270 top
C30  11.43,60.96 180 top
C31  70.87,36.32 270 top
C32  70.87,29.34 270 top
C33  58.42,22.35 270 top
C34  51.31,29.21 270 top
C35  51.31,36.83 270 top
C36  63.5,44.45 90 top
C37  61.47,22.35 270 top
C38  60.96,43.43 90 top
CSL  37.85,10.92 0 top
DRILEGEND  [DRILEGEND]  not placed on the board
E1  3.81,50.8 0 top
E2  52.32,67.31 0 top
E3  32.77,67.31 0 top
E4  3.81,58.42 0 top
E5  15.24,67.31 0 top
J1  6.35,40.64 0 top
J2  75.69,35.56 0 top
J3  29.21,3.05 0 top
J4  6.35,20.32 0 top
J5  53.34,3.17 0 top
JP1  16,26.67 0 top
JP2  16,14.48 0 top
JP3  21.84,54.36 90 top
JP4  39.88,54.36 90 top
MTG1  4.45,4.44 0 top
MTG2  74.3,4.44 0 top
MTG3  74.3,66.67 0 top
MTG4  4.45,66.67 0 top
R1  25.4,39.62 270 top
R2  19.81,43.18 90 top
R3  30.99,40.39 90 top
R4  32.26,36.07 0 top
R5  16.51,42.29 270 top
R6  19.81,38.1 90 top
R7  27.43,32.26 270 top
R8  29.21,32.26 270 top
R9  23.11,18.29 0 top
R10  68.33,58.67 90 top
R11  69.85,58.67 90 top
R12  71.37,58.67 90 top
R13  42.16,28.7 90 top
R14  17.02,20.32 180 top
R15  23.11,20.32 180 top
R16  38.35,20.83 180 top
R17  40.51,28.7 270 top
R18  17.02,18.29 0 top
R19  56.13,23.88 0 top
R20  59.44,43.43 270 top
R21  58.93,11.18 0 top
R22  59.94,22.35 90 top
R23  62.99,22.35 90 top
R24  54.86,11.18 0 top
R25  35.05,56.9 180 top
R26  35.05,59.69 180 top
R27  35.05,61.47 0 top
R28  18.29,59.69 180 top
R29  18.29,54.1 180 top
R30  18.29,56.9 0 top
R31  54.1,23.88 0 top
R32  50.55,35.31 180 top
REF  25.91,22.35 0 top
SCK  33.78,10.92 0 top
SDO  42.42,10.92 0 top
U1  32.51,21.34 270 top
U2  28.19,40.64 270 top
U3  28.19,35.56 270 top
U4  48.01,43.94 90 top
U5  25.65,11.68 270 top
U6  38.1,25.4 0 top
U7  62.74,57.15 270 top
U8  22.61,40.64 270 top
U9  41.4,25.4 180 top
U11  60.96,33.02 270 top
U12  LT1763CS8-1.8  [SO8@1]  53.34,55.88 180 top
U13  LT1763CS8  [SO8@1]  28.19,55.88 180 top
U14  LT1763CS8  [SO8@1]  11.68,55.88 180 top
U$2  [4-LAYER-NAME]  3.81,-1.27 0 top
U$3  [LT-LOGO]  7.75,2.03 0 top
U$4  [TITLEBLK-REV]  not placed on the board
U$6  [LOGO_10MM]  43.94,36.58 0 top
X1  10.16,68.33 0 top
X2  69.34,2.03 0 top

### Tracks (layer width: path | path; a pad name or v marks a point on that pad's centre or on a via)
9V-10V  (via drill 0.3 pad 0.61)
  TOP 0.381: 47.5,54.24 C21.1 49.53,54.24 | 32.13,53.34 32.26,53.21 C25.1 | 28.38,10.73 v28.45,10.67
  TOP 0.508: v47.5,53.09 47.5,54.24 | U12.5 v51.44,51.69 | U13.8 v30.1,51.69 | 32.13,53.34 v31.37,53.34 | U12.8 v55.25,51.69 | v56.26,53.34 56.64,53.34 C22.1 | U14.5 v9.78,51.69 | U14.8 v13.59,51.69 | v15.75,52.45 C28.1 | U5.4 28.38,10.73 | U13.5 v26.29,51.69 | C21.1 v48.51,53.09 | 49.53,54.24 v49.53,53.09
  pour BOTTOM: 0.51,56.13 0.51,46.99 57.91,46.99 57.91,56.13
  pour PWR PLANE: 33.53,15.62 33.53,0.51 0.51,0.51 0.51,56.13 12.7,56.13 12.7,15.62
+1.8V  (via drill 0.3 pad 0.61)
  TOP 0.254: C38.1 60.96,42.93 U11.13 v60.96,39.62 | v60.96,23.49 U11.63 v60.96,26.42 | C37.1 61.47,22.99
  TOP 0.508: C23.1 v54.1,60.96 | v55.12,60.96 C24.1 | U12.2 v53.98,59.94 | U12.1 v55.25,59.94 | 60.96,42.93 v61.6,42.93 | 61.47,22.99 v60.96,23.49
  pour PWR PLANE (no thermals): 62.48,70.61 50.29,70.61 50.29,46.48 59.44,37.34 59.44,22.35 62.48,22.35
CLK
  TOP 0.254: U11.12 61.46,41.9 61.72,42.16 61.98,42.16 62.48,42.67 62.48,43.94 60.71,45.72 35.56,45.72 30.99,41.15 R3.2
CLKOUT
  TOP 0.254: U11.6 64.46,47.7 73.91,57.15 J2.3
CNVST_33
  TOP 0.254: U11.15 59.96,41.77 59.82,41.91 58.93,41.91 56.9,43.94 U4.2 48.77,43.94
CSL  (via drill 0.3 pad 0.61)
  TOP 0.254: U6.2 38.1,24.64
  TOP 0.381: U6.2 38.1,23.37 37.59,22.86 v36.32,22.86 35.05,22.86 34.5,22.31 U1.8
  BOTTOM 0.254: J3.6 33.27,5.08 33.27,6.63 37.59,10.92 CSL.1 36.32,12.45 v36.32,22.86
DB0
  TOP 0.254: J2.37 73.66,13.97 71.88,15.75 71.88,17.02 65.96,22.94 U11.73
DB1
  TOP 0.254: U11.74 66.46,23.71 73.66,16.51 J2.35
DB2
  TOP 0.254: U11.75 66.96,24.23 70.61,20.57 72.14,20.57 73.66,19.05 J2.33
DB3
  TOP 0.254: U11.76 70.01,27.02 71.37,25.65 71.37,24.13 73.91,21.59 J2.31
DB4
  TOP 0.254: U11.77 70.52,27.52 73.91,24.13 J2.29
DB5
  TOP 0.254: U11.78 72.56,28.02 73.91,26.67 J2.27
DB6
  TOP 0.254: U11.84 71.98,31.02 73.79,29.21 J2.25
DB7
  TOP 0.254: U11.89 72.14,33.52 73.91,31.75 J2.23
DB8
  TOP 0.254: U11.92 73.18,35.02 73.91,34.29 J2.21
DB9
  TOP 0.254: U11.96 69.79,37.02 70.61,37.85 72.9,37.85 73.91,36.83 J2.19
DB10
  TOP 0.254: U11.99 72.81,38.52 73.66,39.37 J2.17
DB11
  TOP 0.254: U11.100 70.77,39.02 73.66,41.91 J2.15
DB12
  TOP 0.254: U11.2 66.46,42.08 67.82,43.43 72.64,43.43 73.66,44.45 J2.13
DB13
  TOP 0.254: U11.3 65.96,42.59 69.34,45.97 72.64,45.97 73.66,46.99 J2.11
DB14
  TOP 0.254: U11.4 65.46,43.11 70.87,48.51 72.9,48.51 73.91,49.53 J2.9
DB15
  TOP 0.254: U11.5 64.96,43.62 73.41,52.07 J2.7
DB16  (via drill 0.3 pad 0.61)
  TOP 0.254: U11.71 64.96,21.15 v72.14,13.97
  BOTTOM 0.254: v72.14,13.97 J2.38
DB17  (via drill 0.3 pad 0.61)
  TOP 0.254: U11.72 65.46,21.92 v70.87,16.51
  BOTTOM 0.254: v70.87,16.51 J2.36
DC590_DETECT
  TOP 0.254: U9.4 40.77,24.55 40.77,24.64 40.13,24.64 38.75,26.02 U6.4 38.75,26.42 38.74,26.54 39.62,27.43 39.62,30.99 47.66,39.02 U11.26
DC590VP  (via drill 0.3 pad 0.61)
  TOP 0.254: C16.1 43.94,29.46 43.89,29.41 R13.2 | R13.2 42.22,29.46 42.16,29.46 | 42.16,29.46 R13.2 | v42.16,30.23 42.16,29.46
  BOTTOM 0.254: J3.2 29.21,5.08 30.48,6.35 30.48,21.84 31.75,23.11 35.05,23.11 v42.16,30.23
GND  (via drill 0.3 pad 0.61)
  TOP 0.254: U11.65 61.96,26.4 v61.98,26.42 | U11.60 59.46,26.26 v59.69,26.42 | U3.2 25.52,35.81 v25.4,35.81 | U3.4 25.39,34.81 v25.4,34.8 | U8.3 21.84,39.99 | R6.1 19.81,37.59 | U9.3 40.75,26.3 40.77,26.16 | U6.3 38.77,24.55 38.74,24.51 38.86,24.26 | C34.2 | v54.61,28.7 54.29,29.02 U11.46 52.13,29.02 51.82,28.7 C34.2 | 59.17,21.85 v59.18,21.84 | 60.7,21.85 v60.71,21.84 | 62.22,21.85 v62.23,21.84 | 63.74,21.85 v63.75,21.84 | 71.62,28.84 v71.5,28.83 | 62.46,39.39 62.47,39.39 62.47,39.35 v62.48,39.37 | 62.46,39.39 62.25,39.39 62.23,39.37 61.98,39.62 U11.11 | 62.46,39.39 U11.10 | v62.48,38.35 62.46,39.39 | v54.61,35.81 54.4,36.02 U11.32 51.51,36.02 C35.2 | v67.31,28.19 67.64,28.52 U11.79 70.68,28.52 70.87,28.7 C32.2 | v67.31,35.31 67.52,35.52 U11.93 70.57,35.52 C31.2 | U11.1 66.96,39.62 v67.06,39.62 | v29.08,21.21 29.03,21.01 | U1.3 31.17,21.01 arc90 31.24,21.08 31.24,21.01 31.24,20.95
  TOP 0.381: U13.3 27.56,58.17 | C26.2 32.26,56.64 | C25.2 32.26,54.86 | 47.5,57.66 48.26,57.52 C21.2 48.51,57.66 49.53,57.66 | C2.2 27.43,43.18 | C1.2 21.84,43.18 | U2.3 27.32,39.99 27.31,40 v27.31,39.37 | 21.84,39.99 v21.84,39.12 | C18.2 16.26,22.35 | R18.1 16.26,18.29 | C8.1 24.82,14.93 24.89,14.99 | 23.05,12.63 v22.86,12.7 | C19.2 32,17.53 | C12.1 33.27,17.65 | C11.1 33.27,16 | 28.65,23.82 v28.58,23.88 | 31.95,26.36 v32,26.42 | 38.56,28.78 v38.61,28.83 | C15.1 43.94,26.42 | v40.13,26.16 40.77,26.16 | C36.2 | 57.4,60.96 C24.2 | 56.52,55.24 v56.39,55.24 | C22.2 56.9,54.86 | v61.21,57.4 61.29,57.47 | 61.29,56.82 61.21,56.9 | v61.21,56.39 61.21,56.13 61.26,56.17 | 61.21,57.91 61.26,58.12 | v58.67,44.96 59.94,44.96 60.2,44.7 C38.2 | C4.2 48.77,41.4 | U4.3 49.67,44.59 v49.91,44.83 | R24.2 55.63,11.43 v55.63,11.94 | 71.62,35.82 v71.5,35.81 | C28.2 15.55,54.81 15.49,54.86 | v14.99,56.64 15.04,56.69 | v50.55,36.32 50.56,36.33 | 32.33,21.01 32.33,21.03 v32.51,21.21 32.51,21.01 U1.3 | v52.83,23.88 R31.1 | 31.24,21.01 28.96,21.01 28.96,21.08 28.45,21.08 28.45,21.21
  TOP 0.508: v52.71,56.9 U12.3 | U12.7 v53.98,54.86 | U12.6 v52.71,54.86 | v27.56,57.02 U13.3 | U13.6 v27.56,54.86 | U13.7 v28.83,54.86 | 32.26,56.64 v31.37,56.64 | 32.26,54.86 v31.37,54.86 | 47.5,57.66 v47.5,58.67 | v11.05,56.9 U14.3 | 27.43,43.18 v27.43,43.94 | 21.84,43.18 v21.84,43.94 | C3.2 v26.67,38.1 | 19.81,37.59 v19.81,36.58 | 16.26,22.35 v16.26,23.11 | 16.26,18.29 v16.26,19.05 | 24.89,14.99 v24.13,14.99 | U5.1 23.05,12.63 | U5.2 v22.86,11.68 | 32,17.53 v32,18.29 | 33.27,17.65 v33.27,18.29 | 33.27,16 v33.27,16.76 | C6.1 28.65,23.82 | C9.1 31.95,26.36 | C13.2 38.56,28.78 | R17.1 v40.51,30.23 | 43.94,26.42 v43.18,26.42 | v43.94,27.18 C16.2 | 38.86,24.26 v39.37,24.26 | v50.55,28.7 C34.2 | C33.2 59.17,21.85 | R22.1 60.7,21.85 | C37.2 62.22,21.85 | R23.1 63.74,21.85 | C32.2 71.62,28.84 | v62.74,44.96 C36.2 | v57.4,59.94 57.4,60.96 | 56.9,54.86 56.52,55.24 | 61.29,57.47 U7.2 | v61.21,56.39 61.21,56.9 v61.21,57.4 61.21,57.91 v61.21,58.42 | U7.3 61.29,56.82 | 61.21,56.13 v61.21,55.37 | 61.26,56.17 U7.4 | 61.26,58.12 U7.1 | C14.2 v63.75,60.2 | R20.1 v58.67,43.94 | 48.77,41.4 v48.77,42.16 | C31.2 71.62,35.82 | U14.7 v12.32,55.12 | U14.6 v11.05,55.12 | v14.99,54.86 15.49,54.86 | 15.04,56.69 C29.2 | R30.1 v16.76,56.9 | R5.1 v16.51,44.96 | 50.56,36.33 C35.2 | 34.54,26.42 34.49,26.36 | C21.2 v48.51,58.67 | 49.53,57.66 v49.53,58.67 | C7.2 27.43,23.88 v26.92,23.88 | R27.1 v33.4,61.47 | C10.1 v33.02,27.43
  TOP 0.762: v27.94,21.21 28.45,21.21 v29.08,21.21
  TOP 1.524: v1.27,29.21 v34.54,29.21 34.54,26.42 34.54,24.38 | v40.39,19.3 v40.39,7.37 v26.92,7.37 v26.92,1.27
  BOTTOM 0.508: v72.14,11.43 J2.40 | v72.39,19.05 J2.34 | v72.52,24.13 J2.30 | v72.52,54.61 J2.6 | v72.01,52.07 J2.8 | v72.14,49.53 J2.10 | v72.14,46.99 J2.12 | v72.14,44.45 J2.14 | v72.14,41.91 J2.16 | v72.39,39.37 J2.18 | v72.52,36.83 J2.20 | v72.52,34.29 J2.22 | v72.39,31.75 J2.24 | v72.52,29.21 J2.26 | v72.52,26.67 J2.28 | v72.39,21.59 J2.32 | v72.39,57.15 J2.4
  other vias: 11.43,29.21 24.64,29.21 34.54,26.92 34.54,24.64 40.39,17.02 40.39,14.22 40.39,11.68 40.39,9.4 35.81,7.37 32.26,7.37 29.21,7.37 26.92,3.3 13.97,29.21 16.51,29.21 19.05,29.21 6.35,29.21 3.81,29.21 8.89,29.21 21.59,29.21 27.94,29.21 29.97,29.21 32.26,29.21 38.1,7.37 26.92,5.33 32.51,22.22 32.51,20.19
  pour GND PLANE: 0.51,0.51 0.51,70.61 14.22,70.61 78.23,70.61 78.23,0.51 62.48,0.51
  pour TOP: 31.24,14.99 31.24,19.68 32.21,19.68 32.21,22.48 32.84,22.48 32.84,19.68 33.78,19.68 33.78,14.99
N$1
  TOP 0.254: R14.1 17.78,20.32 17.73,20.37
  TOP 0.508: 17.78,20.32 C17.1 | 17.73,20.37 C18.1 17.73,25.86 JP1.2
N$2
  TOP 0.254: 16.26,20.32 16.26,20.07
  TOP 0.508: R14.2 16.26,20.32 J4.1
N$3  (via drill 0.3 pad 0.61)
  TOP 0.254: U11.23 55.96,39.04 56.64,38.35 v57.4,38.35
  BOTTOM 0.254: v57.4,38.35 56.64,37.59 56.64,16.26 62.23,10.67 62.23,4.32 63.5,3.05 J5.9
N$4  (via drill 0.3 pad 0.61)
  TOP 0.254: U11.24 55.46,39.46 v54.74,38.73 | R24.1 54.15,11.23 54.1,11.18 v54.1,11.94
  BOTTOM 0.254: v54.74,38.73 53.59,37.59 53.59,12.45 v54.1,11.94 54.61,11.43 54.61,4.32 J5.1
N$5  (via drill 0.3 pad 0.61)
  TOP 0.254: v54.61,39.88 54.96,40.25 54.96,40.48 U11.25
  BOTTOM 0.254: v54.61,39.88 54.86,39.88 55.63,39.12 55.63,14.73 57.15,13.21 57.15,4.32 J5.3
N$6  (via drill 0.3 pad 0.61)
  TOP 0.254: U11.22 56.46,39.82 v56.9,39.37 | 59.64,11.12 R21.2 59.69,11.18 v59.69,11.94
  BOTTOM 0.254: v56.9,39.37 56.13,38.61 56.13,15.49 v59.69,11.94 59.69,4.32 J5.5
N$7
  TOP 0.381: R27.2 35.69,61.47 35.69,60.58 | 35.69,60.58 35.69,59.69 R26.1 39.62,59.69 JP4.3 | U13.2 28.83,59.44 29.97,60.58 35.69,60.58
N$9
  TOP 0.254: U11.64 61.46,24.26 62.87,22.86 R23.2
N$10
  TOP 0.254: U3.3 27.43,35.31 27.69,35.05 27.69,32.97 R7.1
N$11
  TOP 0.254: U11.52 55.46,24.05 R19.1 R31.2
N$12
  TOP 0.254: U3.5 29.48,34.81 29.21,34.54 R8.1
N$13
  TOP 0.254: R13.1 42.16,27.94 42.11,27.99 41.4,27.99 | 41.4,27.99 R17.2 | U9.2 41.4,27.99
N$14
  TOP 0.381: R25.1 JP4.2
N$15
  TOP 0.254: U11.33 51.26,35.52 arc90 R32.1
N$17
  TOP 0.254: R10.1 68.33,57.91 67.89,57.47 U7.7
N$18
  TOP 0.254: JP3.2 R30.2 | U14.2 12.32,59.31 13.97,60.96 22.61,60.96 23.37,60.2 23.37,58.42 JP3.2 | R29.1 21.59,54.1 JP3.1 JP3.2
N$19  (via drill 0.3 pad 0.61)
  TOP 0.254: U7.6 69.53,56.82 v69.85,57.15 R11.1 | v72.52,59.69 J2.1
  BOTTOM 0.254: J3.11 39.24,2.92 40.89,1.27 64.77,1.27 69.09,5.59 69.09,56.39 v69.85,57.15 72.39,59.69 v72.52,59.69
N$20
  TOP 0.254: JP3.3 21.59,59.69 R28.1
N$23
  TOP 0.254: R4.1 31.5,36.07 31.24,35.81 U3.7
N$24
  TOP 0.381: 17.73,18.34 R18.2
  TOP 0.508: 17.73,18.34 18.54,17.53 JP2.2
N$25
  TOP 0.254: R4.2 33.02,36.07 41.54,44.59 U4.4
N$26  (1 unrouted)
  TOP 0.254: 22.4,18.34 22.35,18.29 R9.1
  TOP 0.508: 22.4,18.34 R15.2 C17.2 20.78,26.47 JP1.3 | 21.08,14.6 22.35,15.87 22.35,18.29
N$27
  TOP 0.254: 16.76,40.64 16.76,40.7 R5.2 16.51,40.64
  TOP 0.508: 16.76,40.64 C5.1 | J1.1 16.51,40.64
N$28
  TOP 0.254: R2.1 19.81,42.67 | 19.81,40.64 C5.2
  TOP 0.381: C5.2 U8.2
  TOP 0.508: R6.2 19.81,40.64 R2.1
N$29
  TOP 0.254: U3.1 26.42,36.31 26.42,36.32 25.4,37.34 R1.2
N$30
  TOP 0.254: R22.2 59.94,23.62 60.46,24.14 U11.62
N$31
  TOP 0.254: 30.99,39.62 R3.1 30.99,39.99 U2.4
N$32
  TOP 0.254: R16.2 37.59,21.08 37.52,21.01
  TOP 0.381: R16.2 37.59,20.83 37.41,21.01 U1.6
N$34  (via drill 0.3 pad 0.61)
  TOP 0.254: U7.5 70.4,56.17 v71.37,57.15 R12.1
  BOTTOM 0.254: J3.9 37.24,2.9 39.37,0.76 65.02,0.76 69.85,5.59 69.85,55.63 v71.37,57.15 71.37,57.4 73.66,59.69 J2.2
N$36
  TOP 0.381: U2.2 25.65,40.64 25.4,40.39 R1.1 25.35,40.33 25.02,40 23.5,40 23.5,39.99 U8.4
N$39
  TOP 0.254: 29.46,22.35 C6.2 | 27.63,22.35 C7.1
  TOP 0.381: U1.2 29.91,21.66 29.21,22.35
  TOP 0.508: 29.46,22.35 29.21,22.35 27.69,22.35 C7.1 | REF.1 27.63,22.35
N$41
  TOP 0.254: R7.2 29.16,31.55 29.21,31.5 R8.2 34.49,31.55 36.07,29.97 36.07,26.16 37.34,24.89 37.45,24.89 U6.1
N$44
  TOP 0.254: 30.99,20.32 31.02,20.36 U1.4
  TOP 0.381: 30.99,20.3 30.99,20.32 | R15.1 23.75,20.32 23.97,20.3
  TOP 0.508: 30.99,20.32 30.73,20.32 30.53,20.12 C19.1 | 23.97,20.3 30.99,20.3
N$45  (via drill 0.3 pad 0.61)
  TOP 0.254: R12.2 69.9,59.38 69.85,59.44 R11.2 68.38,59.38 | 68.33,59.44 68.38,59.38 | 68.38,59.38 68.27,59.38 68.33,59.44 | 68.33,59.44 R10.2 | 68.33,59.44 v68.33,60.2 C14.1 65.99,58.11 65.79,58.17 U7.8 | J2.39 73.91,11.43 72.9,10.41 v68.07,10.41
  BOTTOM 0.254: J3.10 37.24,5.23 38.23,6.22 42.04,6.22 46.48,1.78 64.52,1.78 68.07,5.33 v68.07,10.41 68.33,10.41 v68.33,60.2
N$50
  TOP 0.381: U13.4 26.29,60.32 26.92,60.96 C27.2
N$51
  TOP 0.254: U11.14 60.46,42.16 60.45,42.16 59.69,42.93 59.44,42.93 R20.2
N$53
  TOP 0.254: U12.4 51.44,60.58 51.82,60.96
  TOP 0.381: 51.82,60.96 C23.2
N$57
  TOP 0.254: C30.2 10.67,60.96 9.78,60.07 U14.4
SCK  (via drill 0.3 pad 0.61)
  TOP 0.254: 35.31,21.72 v35.31,21.84 37.59,21.84 38.86,23.11 44.45,23.11 45.97,24.64 45.97,31.23 R32.2
  TOP 0.381: 35.12,21.66 arc90 v35.31,21.84 35.12,21.66 | 35.12,21.66 U1.7
  BOTTOM 0.254: v35.31,21.84 35.56,21.59 35.56,12.7 SCK.1 30.99,8.13 30.99,5.33 31.22,5.1 J3.4
SDO
  TOP 0.254: U11.34 52.04,35.02 46.99,29.97 46.99,24.38 43.43,20.83 42.42,20.83 | J3.5 33.27,3.05 35.05,1.27 41.66,1.27 43.13,2.74 43.13,9.96 42.42,10.67 SDO.1 | SDO.1 42.37,10.92 | 39.12,21.08 R16.1 42.42,20.83 | SDO.1 42.42,20.83
VCCIO  (via drill 0.3 pad 0.61)
  TOP 0.254: U11.9 62.96,41.88 63.25,42.16 63.47,42.2 v63.5,42.16 | U3.8 29.72,36.45 | 51.3,29.73 C34.1 51.51,29.52 U11.45 54.41,29.52 v54.61,29.72 | v57.67,22.85 v57.66,22.86 | U11.59 58.96,24.29 v58.42,23.75 | 70.99,29.84 C32.1 70.61,29.84 69.79,29.02 U11.80 67.5,29.02 v67.31,29.21 | v67.31,36.32 67.61,36.02 U11.94 69.8,36.02 70.61,36.83 C31.1 | U3.6 30.73,35.31 v31.12,34.92 | v54.61,36.83 54.3,36.52 U11.31 52.13,36.52 52.07,36.58 52.07,37.08 51.82,37.34 C35.1
  TOP 0.381: C27.1 28.45,61.09 v29.21,61.09 | C26.1 32.26,58.17 | R2.2 19.81,43.94 | C1.1 23.37,43.18 | U8.5 23.38,41.29 23.37,41.27 v23.37,41.91 | C2.1 28.83,43.18 | U2.5 28.97,41.29 28.96,41.27 v28.96,41.91 | 29.72,36.45 v29.72,36.83 | v34.8,18.8 C12.2 | C11.2 34.8,16 | 37.45,27.07 v37.34,27.18 | C13.1 37.34,27.94 | U9.5 42.05,24.4 42.29,24.38 | 43.94,24.89 C15.2 43.94,25.15 | C4.1 47.24,41.4 | U4.5 46.34,43.29 v46.23,43.31 | R21.1 58.17,11.18 v58.17,11.94 | v50.55,37.34 50.56,37.33 | 71.62,36.82 v71.5,36.83 | U1.5 34.51,20.36 v34.8,20.07 | R19.2 56.64,23.88 v57.66,22.86
  TOP 0.508: C36.1 v63.5,43.18 v63.5,42.16 | v30.1,57.02 U13.1 | 32.26,58.17 v31.37,58.17 | R26.2 v33.4,59.69 | R25.2 v33.4,56.9 | 19.81,43.94 20.83,44.96 v21.34,44.96 | 23.37,43.18 v23.37,43.94 | 28.83,43.18 v28.83,43.94 | C3.1 v29.72,38.1 | 34.8,16 v34.8,18.8 v34.8,20.07 | U6.5 37.45,27.07 | 37.34,27.94 v37.34,28.83 | 42.29,24.38 v42.67,24.38 | C15.2 v43.94,24.13 | v50.55,29.72 51.3,29.73 | v57.67,22.85 C33.1 v58.42,23.75 | 70.99,29.84 v71.5,29.84 | 47.24,41.4 v47.24,42.16 | 50.56,37.33 C35.1 | C31.1 71.62,36.82
  other vias: 34.8,15.24 34.8,16.76
  pour PWR PLANE (no thermals): 78.23,0.51 34.04,0.51 34.04,25.4 20.83,25.4 20.83,70.61 49.78,70.61 49.78,46.23 58.93,37.08 58.93,21.84 62.99,21.84 62.99,70.61 78.23,70.61
  pour TOP: 34.54,20.57 34.54,14.99 36.58,14.99 36.58,20.57
VCM
  TOP 0.254: 26.42,14.99 C8.2 26.62,14.93 26.42,14.99
  TOP 0.381: U5.6 26.86,12.63 26.67,12.7
  TOP 0.508: 26.67,12.7 26.42,12.95 26.42,14.99 26.42,16 24.13,18.29 R9.2
VDD  (via drill 0.3 pad 0.61)
  TOP 0.254: 33.02,24.89 C10.2 | U1.1 30.99,22.43
  TOP 0.381: U14.1 13.59,59.18 | 33.02,24.89 33.22,24.94
  TOP 0.508: 13.59,59.18 v14.48,59.18 | C30.1 12.7,60.96 v12.95,61.21 | C29.1 v15.75,59.18 | R28.2 v16.76,59.69 | R29.2 v16.76,54.1 | C9.2 v30.99,24.13 30.99,22.43 | v32.77,24.13 33.02,24.89 | 30.99,22.43 31.07,22.43 30.99,22.35 30.99,22.43
  pour PWR PLANE: 33.53,16.13 13.21,16.13 13.21,56.64 0.51,56.64 0.51,70.61 20.32,70.61 20.32,24.89 33.53,24.89
  pour TOP: 33.15,22.99 30.48,22.99 30.48,25.27 33.15,25.27

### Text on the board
BOTTOM: REV 3
tPlace-Top Comp. Outline: LTC CONFIDENTIAL- | FOR CUSTOMER USE ONLY | VDD | VCCIO | 1.8V | VDD | VCCIO | GND | 2.5V | 2.5V | 9V-10V | 3.3V | 5V | LTC23 CTS8- | -BIT HIGH SPEED SAR ADC | Msps | www.linear.com | CLK IN | 100MHz MAX | 3.3Vpp | COUPLING | AC | DC | DEMO | CIRCUIT | VCM | 1563A- | AIN | 0V-4.096V | DC590 | JTAG | 2.048V | 1.024V | (408)432-1900
FAB DWG: LAYER STRUCTURE | 0.0026" | L1-TOP | 10. | 0.0157" | 0.0012" | L2-GND PLANE | 0.062" | 0.0210" | +/-.005" | 0.0012" | L3-PWR PLANE | 10. | 0.0157" | 0.0026" | L4-BOTTOM | 2.80" | NOTES: UNLESS OTHERWISE SPECIFIED | 1. FAB PER IPC-A-600. | 2. MATERIAL: | LEAD FREE ASSEMBLY COMPLIANT, ISOLA FR-370HR | OR EQUIVALENT. | FINISHED THICKNESS TO BE 0.062" +/-0.005" | 4-LAYER BOARD, 2 OZ. CU ON OUTER LAYERS, | 1 OZ. CU ON INNER LAYERS. | FLAMMABILITY RATING: 94 V-2 MINIMUM. | 3. SIZE: | CUT TO DIMENSIONS AND TOLERANCES SHOWN. | 0.00" ARE PRIMARY DATUMS. | 4. FINISH: | SMOBC USING LPI BOTH SIDES, COLOR GREEN. | GOLD IMMERSION. | SILKSCREEN: WHITE NON-CONDUCTIVE EPOXY INK. | 5. DRILL: | PLATE THRU ALL HOLES WITH COPPER, 0.001" THICK MIN. | ALL HOLES SHALL BE DRILLED +/-0.003" WITH | RESPECT TO CTR. OF DRILLED PAD. | ALL HOLES FINISHED SIZE AFTER PLATING. | 6. DROP ALL UNUSED PADS ON INNER LAYERS. | 7. DO NOT ALTER ARTWORK e.g. TO ADD LOGO OR DATE CODE. | PAD SIZE CAN BE MODIFIED TO MEET END FINISH. | 8. PCBS ARE TO BE RoHS COMPLIANT. | 9. SCORING FOR PANELIZED PCB: | 0.017" | 0.00" | 0.02" | XXXXXXXXXXXX | |||||||||||||||||||||||||||||||||||||||||||||||||||||||||||||||||||||||||||||| | XXXXXXXXXXXX | 0.00" | 3.10" | 10. | SUBJECT TO CHANGE BY MANUFACTURE, DEPENDING ON | DIELECTRIC CONSTANT DEVIATIONS. PLEASE CONSULT LTC. | FAB DWG
Document: 3 | PRODUCTION | GUY H. | 01-22-13 | KIM T. | 01-22-13 | GUY H. | 01-22-13 | 12/14-BIT HIGH SPEED SAR ADC | LTC23XXCTS8 FAMILY | DEMO CIRCUIT 1563A | 3 | 1 | 1
Reference: 12/14-BIT HIGH SPEED SAR ADC | 1563A | 3
tDocu-TOP ASSY DWG: 7 | 7 | NOTES: UNLESS OTHERWISE SPECIFIED | 1. WORKMANSHIP SHALL BE IN ACCORDANCE WITH IPC-A-610. | 2. INSTALL SHUNTS ON JUMPERS AS SHOWN. | 3. PARTS TO OMIT WILL BE SPECIFIED ON THE BILL OF MATERIALS. | MASK THE SOLDER STENCIL WHERE SMT PARTS ARE OMITTED. | 4. DEPANELIZE BOARDS AFTER ASSEMBLY AND ROUTE-OUT | THE BREAKOUT TABS ON 4 SIDES OF THE BOARD EDGE. | 5. ASSY PROCESS SHALL INCLUDE: REFLOW SOLDER TOP SIDE SMD. | 6. INSTALL 4 STANDOFF AT 4 CORNERS FROM THE BOTTOM SIDE. | 7. MARK LTC PART NUMBER, ASSY VERSION, -BIT, AND MSPS | WITH BLACK PERMANENT MARKER, APPROX. WHERE SHOWN. | ASSY | U1 | -BIT | Msps | -A | LTC2315CTS8-12 | 12 | 5 | -B | LTC2313CTS8-12 | 12 | 2.5 | -C | LTC2312CTS8-12 | 12 | 0.5 | -F | LTC2314CTS8-14 | 14 | 4.5 | -G | LTC2313CTS8-14 | 14 | 2.5 | -H | LTC2312CTS8-14 | 14 | 0.5 | 7 | ASSY DWG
